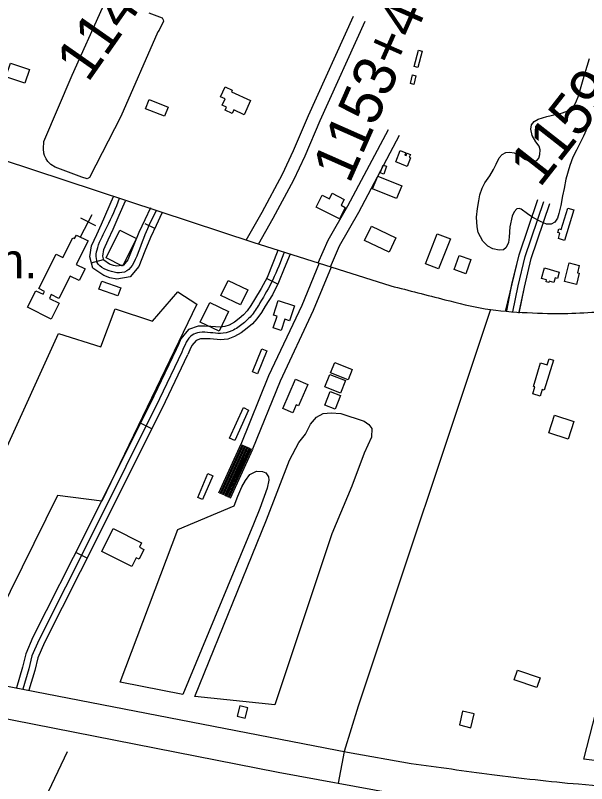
# Model space of a CAD drawing. Extents: x 3855477 to 3893699, y 299188 to 325115.
# Drawn here: x 3867166 to 3868521, y 308321 to 310145 of the extents above; entities that cross this region are included whole.
import ezdxf

# ---------------------------------------------------------------- set-up
doc = ezdxf.new("R2010")
doc.units = 0
for name, color, linetype in [('V-BLDG-OTLN', 7, 'Continuous'), ('V-ROAD-CNTR', 7, 'Continuous'), ('V-SITE-OTLN', 7, 'Continuous'), ('V-SITE-OTLN-IDEN', 7, 'Continuous'), ('V-SITE-VEGE', 7, 'Continuous'), ('V-SURV-IDEN', 7, 'Continuous'), ('V-TOPO-SHOR', 7, 'Continuous')]:
    doc.layers.add(name, color=color, linetype=linetype)

msp = doc.modelspace()

# ---------------------------------------------------------------- linework, layer by layer
at = {"layer": 'V-BLDG-OTLN'}
for points in [[(3868131.3, 310059.6), (3868121.4, 310021.3), (3868112.5, 310023.6), (3868122.4, 310061.9)], [(3867154.5, 310031.6), (3867199.9, 310016.4), (3867189, 309984), (3867143.7, 309999.1)], [(3868116.4, 310001.6), (3868111.8, 309981.1), (3868103.6, 309982.9), (3868108.2, 310003.4)], [(3867724.2, 309942.4), (3867708.8, 309909), (3867684.4, 309920.2), (3867680.7, 309912), (3867664.1, 309919.6), (3867667.5, 309926.9), (3867657.3, 309931.6), (3867664.2, 309946.6), (3867653.1, 309951.8), (3867663.8, 309975), (3867680.8, 309967.1), (3867679.1, 309963.2)], [(3867483.4, 309945.1), (3867528.7, 309927.2), (3867520, 309905.2), (3867474.7, 309923.2)], [(3868095.4, 309786.3), (3868068.6, 309796.9), (3868079.3, 309823.9), (3868092.3, 309818.7), (3868090.2, 309813.3), (3868093, 309812.2), (3868095.1, 309817.7), (3868103.4, 309814.4), (3868100.9, 309807.9), (3868103.5, 309806.9)], [(3868047.1, 309786.5), (3868040.6, 309767.9), (3868032, 309771), (3868038.5, 309789.5)], [(3868025.9, 309763.4), (3868083, 309740.2), (3868070.7, 309710), (3868013.6, 309733.2)], [(3867935, 309662), (3867880.3, 309689.9), (3867894.5, 309717.8), (3867911.2, 309709.3), (3867917.9, 309722.4), (3867946.4, 309707.9), (3867939.2, 309694), (3867948.8, 309689.1)], [(3868491.1, 309683.1), (3868468.9, 309610.7), (3868454.4, 309615.1), (3868458.2, 309627.5), (3868453.1, 309629), (3868455.8, 309637.8), (3868460.9, 309636.2), (3868476.6, 309687.5)], [(3867994.9, 309610.7), (3868011.1, 309644.5), (3868069, 309616.7), (3868052.8, 309582.9)], [(3867453.5, 309615.2), (3867420.7, 309549.6), (3867381.4, 309569.2), (3867414.2, 309634.9)], [(3868198.2, 309614.3), (3868170.1, 309543), (3868139, 309555.3), (3868167.1, 309626.5)], [(3867251.6, 309423.8), (3867195.4, 309452.1), (3867215.1, 309491.2), (3867232, 309482.7), (3867235.5, 309489.6), (3867222, 309496.4), (3867263.3, 309578.2), (3867279.1, 309570.3), (3867302.7, 309617.1), (3867306.8, 309615), (3867311.1, 309623.4), (3867339.2, 309609.3), (3867311, 309553.5), (3867331.8, 309543), (3867317.8, 309515.1), (3867296.4, 309525.9), (3867269.6, 309472.8), (3867251.7, 309481.9), (3867247.2, 309473), (3867270.5, 309461.3)], [(3868219.1, 309574.9), (3868246.7, 309565.1), (3868234.7, 309531.3), (3868207.1, 309541.2)], [(3868469.2, 309513.2), (3868480.3, 309557.2), (3868504.1, 309551.2), (3868499.6, 309533.7), (3868504.1, 309532.5), (3868497.4, 309506)], [(3868421.6, 309545.3), (3868456.5, 309534.9), (3868452, 309519.9), (3868446.7, 309521.5), (3868443.4, 309510.7), (3868432.9, 309513.8), (3868431.9, 309510.5), (3868425.1, 309512.6), (3868426.4, 309516.9), (3868414.2, 309520.5)], [(3867671.1, 309515.5), (3867717.5, 309493.2), (3867700.5, 309457.9), (3867654.1, 309480.2)], [(3867371.7, 309514.1), (3867416.2, 309498.2), (3867409.2, 309478.7), (3867364.7, 309494.6)], [(3867627.4, 309463.4), (3867672.2, 309441.5), (3867649.5, 309394.9), (3867604.6, 309416.8)], [(3867790, 309467.9), (3867828.2, 309455.2), (3867816.5, 309419.9), (3867805.8, 309423.4), (3867797, 309396.8), (3867778.2, 309403.1), (3867787.3, 309430.6), (3867778.6, 309433.5)], [(3867762.5, 309348.3), (3867740.5, 309294), (3867728.8, 309298.7), (3867750.8, 309353.1)], [(3867923.9, 309320.8), (3867965.3, 309304.5), (3867955.5, 309279.7), (3867914.2, 309296)], [(3868395.5, 309264), (3868412.2, 309319.6), (3868427.7, 309314.9), (3868432.2, 309329.8), (3868442.6, 309326.7), (3868421.1, 309255), (3868415.8, 309256.6), (3868411.1, 309241), (3868393.5, 309246.3), (3868398.6, 309263.1)], [(3867830.6, 309281.5), (3867859.9, 309268.9), (3867838, 309217.9), (3867832.8, 309220.1), (3867824.7, 309201.1), (3867800.5, 309211.5)], [(3867912.5, 309292.4), (3867949.6, 309277.8), (3867937.8, 309248.2), (3867900.8, 309262.9)], [(3867937.3, 309242.7), (3867924.7, 309210), (3867900.4, 309219.4), (3867913, 309252.1)], [(3867719.8, 309208), (3867686.9, 309135.6), (3867674.6, 309141.2), (3867707.5, 309213.6)], [(3868445.5, 309195.7), (3868491.1, 309180.5), (3868477.3, 309139), (3868431.7, 309154.2)], [(3867634.6, 309052), (3867610.6, 308995.7), (3867599, 309000.7), (3867623, 309056.9)], [(3867398.2, 308926.4), (3867465.7, 308892.6), (3867460.6, 308882.4), (3867471.5, 308876.9), (3867459.9, 308853.7), (3867452.9, 308857.3), (3867442.6, 308836.7), (3867371.2, 308872.4)], [(3868403.5, 308549.3), (3868349.9, 308567.1), (3868357.6, 308590.2), (3868411.2, 308572.3)], [(3867692.4, 308481.2), (3867711.7, 308476.3), (3867717.9, 308501.3), (3867698.6, 308506.1)], [(3868219.6, 308460.3), (3868246.9, 308453.8), (3868254.6, 308486.4), (3868227.3, 308492.9)]]:
    msp.add_lwpolyline(points, close=True, dxfattribs=at)
at = {"layer": 'V-ROAD-CNTR'}
for p, q in [((3867497.1, 309639), (3867474.6, 309649.6)), ((3867346.6, 309557.6), (3867375.6, 309565.1)), ((3867788.8, 309507), (3867762.1, 309520.5)), ((3867489.8, 309163.6), (3867462.9, 309177)), ((3867336.7, 308856.6), (3867309.9, 308870.1))]:
    msp.add_line(p, q, dxfattribs=at)
for points in [[(3867713.7, 309611.4), (3867752, 309678), (3867799.9, 309767.9), (3867826.5, 309823.8), (3867861.6, 309907), (3867968.8, 310143.1)], [(3867742.8, 309601.9), (3867778.2, 309663.4), (3867826.7, 309754.4), (3867853.8, 309811.5), (3867889.1, 309895), (3867996.1, 310130.7)], [(3867884.9, 309557.1), (3867908.7, 309610.9), (3867954.9, 309692.3), (3868051.2, 309874.2)], [(3866985.9, 309852), (3867729.6, 309606.1), (3868057.1, 309502.7)], [(3867913.7, 309548), (3867935.6, 309597.4), (3867981.2, 309677.9), (3868077.7, 309860.2)], [(3860983.7, 309748.8), (3862185, 309519.4), (3863555.5, 309254), (3864992.1, 308971.5), (3866162.7, 308746.1), (3867159.7, 308550.2), (3867954.5, 308395.7), (3868105, 308368.9)], [(3867514.2, 309675.4), (3867500.6, 309646.3), (3867487.1, 309617.6), (3867473.7, 309584.7), (3867459.5, 309548.9), (3867438.6, 309524.2), (3867406.7, 309518.8), (3867390.8, 309522.1), (3867376.1, 309527.4), (3867349.8, 309545.1), (3867342.9, 309571.9), (3867347.2, 309597.8), (3867359.4, 309624.7), (3867370.7, 309649.5), (3867399.5, 309715.2)], [(3860884.4, 309700.6), (3862044.8, 309470.5), (3862858.2, 309310.5), (3864777.9, 308942), (3865687.7, 308763.4), (3866820.3, 308539.2), (3867789.8, 308348.3), (3868065.6, 308297.8)], [(3867487.1, 309688.2), (3867473.4, 309659.1), (3867459.6, 309629.6), (3867445.8, 309595.9), (3867433.4, 309564.5), (3867422.8, 309551.9), (3867407.3, 309549.3), (3867399.1, 309551), (3867389.8, 309554.4), (3867376, 309563.6), (3867373.5, 309573.2), (3867376.2, 309589), (3867386.8, 309612.3), (3867398.1, 309637.3), (3867412.9, 309670.9), (3867427.6, 309704.5)], [(3868328.9, 309442.2), (3868361.4, 309576.3), (3868406, 309707.9)], [(3868331.6, 309441.9), (3868344.4, 309506), (3868361.4, 309576.3), (3868406, 309707.9)], [(3868332, 309443.8), (3868344.4, 309506), (3868361.4, 309576.3), (3868406, 309707.9)], [(3868346.7, 309440.8), (3868359, 309502.8), (3868375.8, 309572.1), (3868420.2, 309703.1)], [(3868361.4, 309437.9), (3868373.7, 309499.5), (3868390.2, 309567.9), (3868434.4, 309698.3)], [(3868361.8, 309440), (3868373.7, 309499.5), (3868390.2, 309567.9), (3868434.4, 309698.3)], [(3867789.1, 309586.4), (3867763.3, 309522.9), (3867749.7, 309496.2), (3867733.8, 309470.1), (3867725.1, 309456.3), (3867716.1, 309443.7), (3867707.4, 309434.1), (3867697.4, 309425.3), (3867685.9, 309416.6), (3867673.6, 309409.8), (3867663, 309405.9), (3867652.5, 309404.7), (3867629.8, 309406.6), (3867615.9, 309407), (3867600.1, 309406.7), (3867577.2, 309398.9), (3867559, 309376.8), (3867553, 309363.3), (3867547.8, 309351.6)], [(3867818.1, 309578.1), (3867804.2, 309544), (3867790.6, 309510.4), (3867776, 309481.6), (3867759.3, 309454.3), (3867750, 309439.6), (3867739.4, 309424.8), (3867728.5, 309412.7), (3867716.4, 309402), (3867702.3, 309391.4), (3867686.1, 309382.4), (3867670, 309376.5), (3867653, 309374.5), (3867628.1, 309376.7), (3867615.8, 309377), (3867605.4, 309376.8), (3867595, 309373.2), (3867584.7, 309360.8), (3867580.4, 309351.1), (3867575.2, 309339.4)], [(3867886.9, 309556.4), (3867845.6, 309456.2), (3867767.1, 309288.8), (3867701.2, 309126.3)], [(3867915.6, 309547.4), (3867873.1, 309444.1), (3867794.6, 309276.7), (3867729, 309115.1)], [(3868293.7, 309446.3), (3867979.8, 308504.8), (3867946.5, 308397.3), (3867932.3, 308322.2)], [(3867548, 309352), (3867494.8, 309241), (3867335.3, 308920.4), (3867208.1, 308668.4), (3867191.3, 308629), (3867183.5, 308597.4), (3867169, 308548.4)], [(3867561.5, 309345.5), (3867508.3, 309234.4), (3867348.7, 308913.6), (3867221.7, 308662), (3867205.5, 308624.2), (3867198, 308593.5), (3867183.8, 308545.6)], [(3867575, 309339), (3867521.7, 309227.8), (3867362.1, 308906.9), (3867235.3, 308655.7), (3867219.8, 308619.5), (3867212.5, 308589.5), (3867198.6, 308542.7)], [(3867701.4, 309126.9), (3867648.4, 309010.5)], [(3867704.2, 309125.7), (3867651.1, 309009.2)], [(3867706.9, 309124.4), (3867653.9, 309008)], [(3867709.6, 309123.2), (3867656.6, 309006.8)], [(3867712.4, 309121.9), (3867659.3, 309005.5)], [(3867715.1, 309120.7), (3867662.1, 309004.3)], [(3867717.8, 309119.5), (3867664.8, 309003)], [(3867720.6, 309118.2), (3867667.5, 309001.8)], [(3867723.3, 309117), (3867670.3, 309000.5)], [(3867726, 309115.7), (3867673, 308999.3)], [(3867728.7, 309114.5), (3867675.7, 308998.1)]]:
    msp.add_lwpolyline(points, dxfattribs=at)
for points in [[(3867500.7, 309681.8), (3867473.3, 309623.6), (3867446.5, 309556.7), (3867430.7, 309538), (3867407, 309534), (3867382.9, 309540.9), (3867362.9, 309554.4), (3867358.2, 309572.6), (3867361.7, 309593.4), (3867384.4, 309643.4), (3867413.8, 309710.5)], [(3867803.8, 309582.7), (3867776.9, 309516.7), (3867746.6, 309462.2), (3867727.8, 309434.2), (3867706.9, 309413.7), (3867679.9, 309396.1), (3867652.7, 309389.6), (3867629, 309391.6), (3867602.8, 309391.8), (3867586.1, 309386), (3867571.9, 309368.8), (3867561.5, 309345.5)], [(3868057.1, 309502.7), (3868185.4, 309469.9), (3868281.1, 309448.4), (3868380.8, 309439.1), (3868476.5, 309437.3), (3868552.9, 309441.2)], [(3868105, 308368.9), (3868296.5, 308343.1), (3868502.1, 308320.2), (3868771.3, 308304.4), (3869058.6, 308292.7), (3869255.8, 308301), (3869428.7, 308307.8)]]:
    msp.add_spline(points, degree=3, dxfattribs=at)
at = {"layer": 'V-SITE-OTLN'}
for p, q in [((3867321.1, 309618.9), (3867348.7, 309672.2)), ((3867357.2, 309645.2), (3867321.7, 309663.6))]:
    msp.add_line(p, q, dxfattribs=at)
at = {"layer": 'V-SITE-VEGE'}
for points in [[(3867483.1, 310151), (3867514.6, 310138.7), (3867516.9, 310134.5), (3867518.1, 310130.9), (3867507.7, 310110.1), (3867504.7, 310106), (3867416.4, 309905.1), (3867342.5, 309759.6), (3867336.5, 309756.7), (3867324, 309761), (3867260.9, 309784.5), (3867250.8, 309790.5), (3867243.2, 309797.8), (3867239.1, 309804.4), (3867235.6, 309812.2), (3867233.8, 309817.6), (3867232.8, 309827.8), (3867233.6, 309845.1), (3867301, 310002.6), (3867372.7, 310163)], [(3868522.8, 309877.9), (3868513.9, 309858.2), (3868506.3, 309841.9), (3868497.5, 309825), (3868489, 309808), (3868481.3, 309788.6), (3868472.1, 309756), (3868467.8, 309733.8), (3868464.1, 309716.4), (3868460, 309693.7), (3868455.9, 309674.4), (3868452.1, 309663.6), (3868446, 309653.7), (3868437.5, 309649), (3868426.6, 309649.4), (3868411.8, 309655.2), (3868394.1, 309664.7), (3868381.2, 309673.5), (3868366.5, 309685.1), (3868361.2, 309686.2), (3868356, 309685.2), (3868349.9, 309678.4), (3868345.2, 309667.9), (3868339.4, 309642.8), (3868338, 309618.2), (3868336.2, 309605.5), (3868330.2, 309593.6), (3868324.2, 309588.6), (3868313.8, 309587.4), (3868298.8, 309590.5), (3868287.1, 309596.9), (3868274.9, 309608.9), (3868264.4, 309629.6), (3868261.9, 309642.6), (3868260.5, 309665.5), (3868262.5, 309686.7), (3868265.5, 309704.3), (3868268.5, 309718.8), (3868273.3, 309734.9), (3868279.9, 309747), (3868291.5, 309764.2), (3868300.7, 309779.2), (3868307, 309791.3), (3868314.2, 309806.4), (3868321.3, 309814.4), (3868329.7, 309819.1), (3868339, 309819.7), (3868349.4, 309818.7), (3868360.8, 309814), (3868375.1, 309803.3), (3868387.6, 309797.8), (3868397.2, 309798), (3868404.3, 309801), (3868408.3, 309805.9), (3868410.6, 309814.9), (3868411.1, 309825.7), (3868408.6, 309834), (3868401.3, 309844.7), (3868392, 309859.5), (3868388.8, 309874.7), (3868391, 309885.3), (3868396.8, 309892.9), (3868406.4, 309898.2), (3868426.9, 309904.8), (3868450.6, 309910.5), (3868463.9, 309913.2), (3868480.9, 309919.4), (3868490.5, 309927.1), (3868497.8, 309941.6), (3868501.4, 309951.3), (3868517.1, 310006.1), (3868527.9, 310042.5)], [(3868686.7, 308357.9), (3868514.6, 308379), (3868615, 308769.9)]]:
    msp.add_lwpolyline(points, dxfattribs=at)
for points in [[(3867551.5, 309488.6), (3867597, 309459.3), (3867371.6, 308991.5), (3867266, 309005), (3867069.4, 308606.8), (3866839.1, 308676.6), (3866867.9, 308807), (3867059.8, 309115.2), (3867138.9, 309103.9), (3867268.4, 309389.6), (3867369.2, 309358.1), (3867402.8, 309448.1), (3867491.5, 309418.8)], [(3867917.3, 308914.3), (3867781.7, 308507.9), (3867592.2, 308528.1), (3867762, 308947), (3867816.6, 309088.9), (3867839, 309131.1), (3867854.5, 309150.3), (3867866.8, 309174.3), (3867880.6, 309191.4), (3867896.4, 309200.1), (3867915.3, 309201.5), (3867938.4, 309199.7), (3867993.7, 309181.7), (3868004.6, 309173.7), (3868011.8, 309164.2), (3868011.1, 309143.3), (3867993.9, 309105.7), (3867964.7, 309026.9)], [(3867731, 308937.4), (3867563.4, 308532.6), (3867414.7, 308561.8), (3867551.5, 308924), (3867685.4, 308980.3), (3867694.5, 309003.8), (3867703.7, 309025.7), (3867712.2, 309040.8), (3867722.9, 309054.9), (3867738.7, 309062.5), (3867752.3, 309061.9), (3867760.7, 309059.1), (3867766.9, 309049.6), (3867767.3, 309041.8), (3867763.9, 309022.4), (3867746.1, 308974.4)]]:
    msp.add_lwpolyline(points, close=True, dxfattribs=at)
at = {"layer": 'V-TOPO-SHOR'}
msp.add_lwpolyline([(3867289.5, 308396.9), (3867236.8, 308286.6), (3867179, 308154.7), (3867115.5, 308025.5)], dxfattribs=at)

# ---------------------------------------------------------------- texts
at = {"layer": 'V-SITE-OTLN-IDEN'}
msp.add_text('Ch.', height=83, rotation=0, dxfattribs=at).set_placement((3867045.6, 309520.7))
at = {"layer": 'V-SURV-IDEN'}
for s, rotation, p in [('1147+77.0', 54.9867, (3867338.3, 309983.1)), ('1153+41.8', 66.1394, (3867958.8, 309742.9)), ('1159+15.7', 51.9106, (3868410.2, 309733.7))]:
    msp.add_text(s, height=100, rotation=rotation, dxfattribs=at).set_placement(p)

doc.saveas('drawing.dxf')
